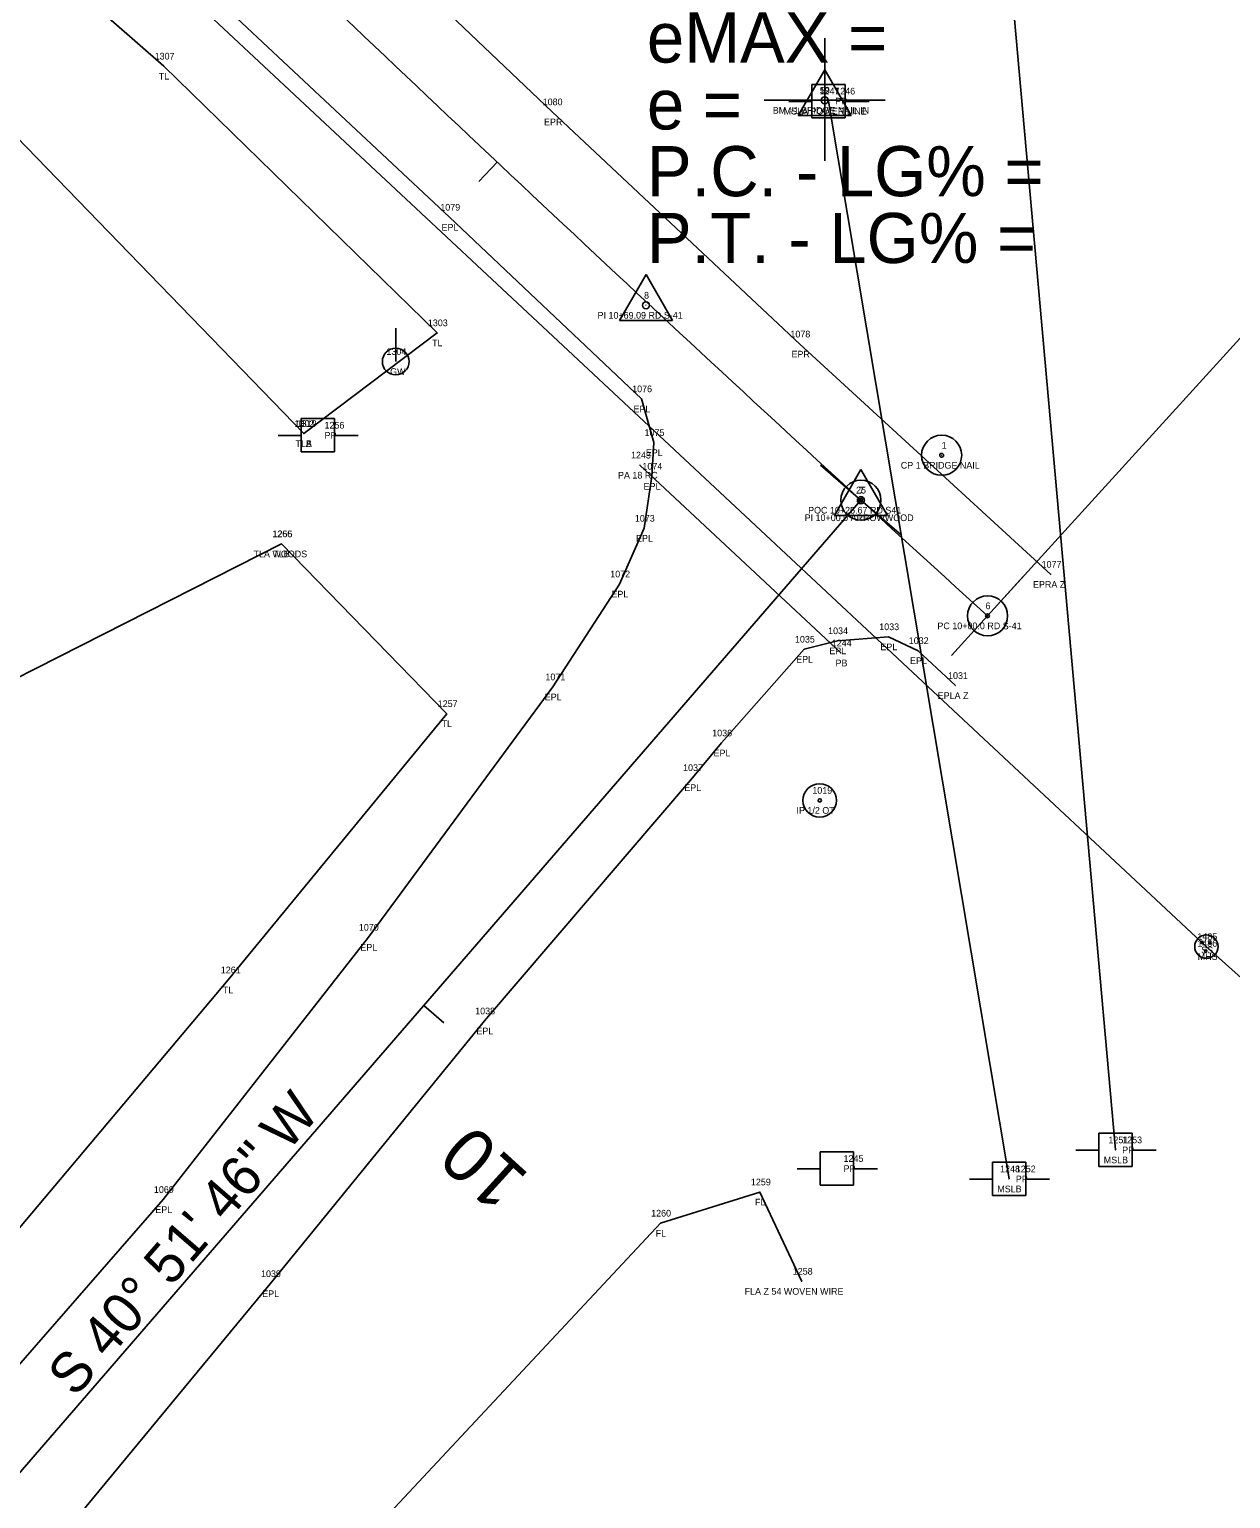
# Model space of a CAD drawing. Extents: x 1812340 to 1815011, y 1177659 to 1180159.
# Drawn here: x 1813923.6 to 1814103.3, y 1178289.1 to 1178509 of the extents above; entities that cross this region are included whole.
import ezdxf

# ---------------------------------------------------------------- set-up
doc = ezdxf.new("R2010")
doc.units = 0
for name, color, linetype in [('RD_EX_DR_Inlet', 7, 'Continuous'), ('RD_EX_DR_Pipe', 7, 'Continuous'), ('RD_EX_DR_Pipe_txCode', 7, 'Continuous'), ('RD_EX_DV_Prop_txCode', 7, 'Continuous'), ('RD_EX_DV_PropPin', 7, 'Continuous'), ('RD_EX_Fence_Other', 7, 'Continuous'), ('RD_EX_Fence_Other_txCode', 7, 'Continuous'), ('RD_EX_Misc', 7, 'Continuous'), ('RD_EX_Misc_txCode', 7, 'Continuous'), ('RD_EX_Road', 7, 'Continuous'), ('RD_EX_Road_txCode', 7, 'Continuous'), ('RD_EX_UT', 7, 'Continuous'), ('RD_EX_UT_txCode', 7, 'Continuous'), ('RD_EX_VEG', 7, 'Continuous'), ('RD_EX_VEG_txCode', 7, 'Continuous'), ('RD_HC_CL', 7, 'Continuous'), ('RD_HC_Data', 7, 'Continuous'), ('RD_HC_Data_Tic', 7, 'Continuous'), ('RD_HC_TX_Sta50', 7, 'Continuous'), ('RD_HC_txCode', 7, 'Continuous'), ('RD_SMD_Locator', 7, 'Continuous')]:
    doc.layers.add(name, color=color, linetype=linetype)

msp = doc.modelspace()

# ---------------------------------------------------------------- linework, layer by layer
at = {"layer": 'RD_EX_DR_Inlet'}
for centre, radius in [((1814099.72, 1178371.7), 1.75), ((1814099.05, 1178372.33), 0.175), ((1814100.28, 1178372.26), 0.175), ((1814099.63, 1178371.03), 0.175)]:
    msp.add_circle(centre, radius, dxfattribs=at)
at = {"layer": 'RD_EX_DR_Pipe'}
msp.add_line((1814014.96, 1178443.75), (1814045.01, 1178415.64), dxfattribs=at)
at = {"layer": 'RD_EX_DV_PropPin'}
for radius in [2.5, 0.25]:
    msp.add_circle((1814041.85, 1178393.58), radius, dxfattribs=at)
at = {"layer": 'RD_EX_Fence_Other'}
msp.add_lwpolyline([(1814039.17, 1178321.6), (1814032.91, 1178334.96), (1814018.04, 1178330.3), (1813949.86, 1178257.34), (1813966.14, 1178241)], dxfattribs=at)
at = {"layer": 'RD_EX_Misc'}
for p, q in [((1814068.17, 1178541.96), (1814086.12, 1178341.27)), ((1814043.18, 1178498.23), (1814070.2, 1178336.93))]:
    msp.add_line(p, q, dxfattribs=at)
at = {"layer": 'RD_EX_Road'}
for points in [[(1814076.45, 1178427.4), (1814038.86, 1178461.87), (1814001.83, 1178496.62), (1813965.15, 1178531.54), (1813928.08, 1178567.1), (1813892.01, 1178601.23), (1813854.54, 1178636.51), (1813817.44, 1178670.03), (1813779.87, 1178701.64)], [(1813829.87, 1178208.6), (1813830.81, 1178209.56), (1813845.51, 1178227.94), (1813874.69, 1178258.74), (1813910.02, 1178295.38), (1813943.63, 1178333.84), (1813974.31, 1178373.09), (1814001.91, 1178410.56), (1814011.9, 1178425.95), (1814015.58, 1178434.3), (1814016.71, 1178442.08), (1814017.03, 1178447.13), (1814015.19, 1178453.67), (1813986.47, 1178480.85), (1813949.15, 1178515.86)], [(1814062.16, 1178410.76), (1814056.57, 1178415.98), (1814052.15, 1178418.06), (1814044.5, 1178417.46), (1814039.53, 1178416.2), (1814027.18, 1178402.17), (1814022.8, 1178396.98), (1813991.69, 1178360.57), (1813959.64, 1178321.24), (1813927.09, 1178281.88), (1813899.48, 1178251.69), (1813888.9, 1178240.78), (1813846.63, 1178195.79)]]:
    msp.add_lwpolyline(points, dxfattribs=at)
at = {"layer": 'RD_EX_UT'}
for p, q in [((1814045.67, 1178500.74), (1814040.67, 1178500.74)), ((1814040.67, 1178500.74), (1814040.67, 1178495.74)), ((1814045.67, 1178495.74), (1814045.67, 1178500.74)), ((1814037.24, 1178498.17), (1814040.71, 1178498.17)), ((1814045.6, 1178498.17), (1814049.24, 1178498.17)), ((1814040.67, 1178495.74), (1814045.67, 1178495.74)), ((1813978.41, 1178459.26), (1813978.41, 1178464.26)), ((1813969.24, 1178450.74), (1813964.24, 1178450.74)), ((1813964.24, 1178450.74), (1813964.24, 1178445.74)), ((1813969.24, 1178445.74), (1813969.24, 1178450.74)), ((1813960.81, 1178448.18), (1813964.28, 1178448.18)), ((1813969.17, 1178448.18), (1813972.81, 1178448.18)), ((1813964.24, 1178445.74), (1813969.24, 1178445.74)), ((1814088.61, 1178343.78), (1814083.61, 1178343.78)), ((1814083.61, 1178343.78), (1814083.61, 1178338.78)), ((1814088.61, 1178338.78), (1814088.61, 1178343.78)), ((1814046.91, 1178340.99), (1814041.91, 1178340.99)), ((1814041.91, 1178340.99), (1814041.91, 1178335.99)), ((1814046.91, 1178335.99), (1814046.91, 1178340.99)), ((1814080.18, 1178341.22), (1814083.65, 1178341.22)), ((1814088.54, 1178341.22), (1814092.18, 1178341.22)), ((1814038.48, 1178338.43), (1814041.95, 1178338.43)), ((1814046.84, 1178338.43), (1814050.48, 1178338.43)), ((1814072.69, 1178339.44), (1814067.69, 1178339.44)), ((1814067.69, 1178339.44), (1814067.69, 1178334.44)), ((1814072.69, 1178334.44), (1814072.69, 1178339.44)), ((1814083.61, 1178338.78), (1814088.61, 1178338.78)), ((1814064.26, 1178336.88), (1814067.73, 1178336.88)), ((1814072.62, 1178336.88), (1814076.26, 1178336.88)), ((1814041.91, 1178335.99), (1814046.91, 1178335.99)), ((1814067.69, 1178334.44), (1814072.69, 1178334.44))]:
    msp.add_line(p, q, dxfattribs=at)
msp.add_lwpolyline([(1814122.48, 1178351.31), (1814099.73, 1178371.68), (1813807.05, 1178645.14), (1813817.45, 1178777.9), (1813883.81, 1178790.87)], dxfattribs=at)
msp.add_circle((1813978.41, 1178459.26), 2, dxfattribs=at)
at = {"layer": 'RD_EX_VEG'}
for points in [[(1813964.65, 1178448.48), (1813984.61, 1178463.55), (1813943.71, 1178503.46), (1813904.65, 1178537.57), (1813863.79, 1178578.71), (1813833.99, 1178603.93), (1813823.24, 1178594.53), (1813964.65, 1178448.48)], [(1813961.33, 1178431.97), (1813986.04, 1178406.55), (1813953.31, 1178366.71), (1813903.24, 1178307.28), (1813881.24, 1178391.37), (1813961.33, 1178431.97)]]:
    msp.add_lwpolyline(points, dxfattribs=at)
at = {"layer": 'RD_HC_CL'}
msp.add_line((1814048.02, 1178438.51), (1813851.74, 1178211.63), dxfattribs=at)
msp.add_arc((1817921.84, 1182660.75), 5730.08, 226.33932, 227.720866, dxfattribs=at)
at = {"layer": 'RD_HC_Data'}
for p, q in [((1814042.6, 1178489.32), (1814042.6, 1178507.65)), ((1814066.97, 1178421.2), (1814145.47, 1178507.54)), ((1814038.63, 1178496.06), (1814042.6, 1178502.94)), ((1814042.6, 1178502.94), (1814046.57, 1178496.06)), ((1814033.56, 1178498.36), (1814051.64, 1178498.36)), ((1814038.63, 1178496.06), (1814046.57, 1178496.06)), ((1814011.88, 1178465.39), (1814015.86, 1178472.27)), ((1814015.86, 1178472.27), (1814019.83, 1178465.39)), ((1814011.88, 1178465.39), (1814019.83, 1178465.39)), ((1814044.05, 1178436.22), (1814048.02, 1178443.1)), ((1814048.02, 1178443.1), (1814051.99, 1178436.22)), ((1814044.05, 1178436.22), (1814051.99, 1178436.22))]:
    msp.add_line(p, q, dxfattribs=at)
for centre, radius in [((1814042.6, 1178498.36), 0.529), ((1814015.86, 1178467.68), 0.529), ((1814060.1, 1178445.23), 3), ((1814060.1, 1178445.23), 0.282), ((1814048.02, 1178438.51), 3), ((1814048.02, 1178438.51), 0.529), ((1814048.02, 1178438.51), 0.282), ((1814066.97, 1178421.2), 3), ((1814066.97, 1178421.2), 0.282)]:
    msp.add_circle(centre, radius, dxfattribs=at)
at = {"layer": 'RD_HC_Data_Tic'}
for p, q in [((1813993.57, 1178489.12), (1813990.83, 1178486.21)), ((1814048.02, 1178438.51), (1814041.97, 1178443.74)), ((1814048.02, 1178438.51), (1814054.07, 1178433.28)), ((1814066.97, 1178421.2), (1814072.35, 1178427.12)), ((1814066.97, 1178421.2), (1814061.59, 1178415.28)), ((1813982.59, 1178362.88), (1813985.62, 1178360.27))]:
    msp.add_line(p, q, dxfattribs=at)
at = {"layer": 'RD_SMD_Locator'}
for centre in [(1813943.71, 1178503.46), (1814042.6, 1178498.36), (1814043.18, 1178498.23), (1814001.83, 1178496.62), (1813986.47, 1178480.85), (1814015.86, 1178467.68), (1813984.61, 1178463.55), (1814038.86, 1178461.87), (1814015.19, 1178453.67), (1813964.65, 1178448.48), (1813964.65, 1178448.48), (1814017.03, 1178447.13), (1814060.1, 1178445.23), (1814014.96, 1178443.75), (1814016.71, 1178442.08), (1814048.02, 1178438.51), (1814048.02, 1178438.51), (1814015.58, 1178434.3), (1813961.33, 1178431.97), (1813961.33, 1178431.97), (1814076.45, 1178427.4), (1814011.9, 1178425.95), (1814066.97, 1178421.2), (1814052.15, 1178418.06), (1814039.53, 1178416.2), (1814044.5, 1178417.46), (1814045.01, 1178415.64), (1814056.57, 1178415.98), (1814001.91, 1178410.56), (1814062.16, 1178410.76), (1813986.04, 1178406.55), (1814027.18, 1178402.17), (1814022.8, 1178396.98), (1813974.31, 1178373.09), (1814099.73, 1178371.68), (1813953.31, 1178366.71), (1813991.69, 1178360.57), (1814086.12, 1178341.27), (1814070.2, 1178336.93), (1814032.91, 1178334.96), (1813943.63, 1178333.84), (1814018.04, 1178330.3), (1813959.64, 1178321.24), (1814039.17, 1178321.6)]:
    msp.add_circle(centre, 0.001, dxfattribs=at)

# ---------------------------------------------------------------- texts
at = {"layer": 'RD_EX_DR_Pipe_txCode'}
for s, p in [('1243', (1814013.62, 1178444.75)), ('PA 18 RC', (1814011.67, 1178441.75)), ('1244', (1814043.66, 1178416.64)), ('PB', (1814044.23, 1178413.64))]:
    msp.add_text(s, height=1, dxfattribs=at).set_placement(p)
at = {"layer": 'RD_EX_DV_Prop_txCode'}
for s, p in [('1019', (1814040.75, 1178394.58)), ('IP 1/2 OT', (1814038.38, 1178391.58))]:
    msp.add_text(s, height=1, dxfattribs=at).set_placement(p)
at = {"layer": 'RD_EX_Fence_Other_txCode'}
for s, p in [('1259', (1814031.56, 1178335.96)), ('1260', (1814016.63, 1178331.3)), ('FL', (1814032.18, 1178332.96)), ('FL', (1814017.31, 1178328.3)), ('1258', (1814037.82, 1178322.6)), ('FLA Z 54 WOVEN WIRE', (1814030.62, 1178319.6))]:
    msp.add_text(s, height=1, dxfattribs=at).set_placement(p)
at = {"layer": 'RD_EX_Misc_txCode'}
for s, p in [('1247', (1814041.83, 1178499.23)), ('MSLA POWER LINE', (1814036.47, 1178496.23)), ('1251', (1814085.06, 1178342.27)), ('1248', (1814068.85, 1178337.93)), ('MSLB', (1814084.36, 1178339.27)), ('MSLB', (1814068.43, 1178334.93))]:
    msp.add_text(s, height=1, dxfattribs=at).set_placement(p)
at = {"layer": 'RD_EX_Road_txCode'}
for s, p in [('1080', (1814000.4, 1178497.62)), ('EPR', (1814000.6, 1178494.62)), ('1079', (1813985.08, 1178481.85)), ('EPL', (1813985.26, 1178478.85)), ('1078', (1814037.47, 1178462.87)), ('EPR', (1814037.63, 1178459.87)), ('1076', (1814013.79, 1178454.67)), ('EPL', (1814013.99, 1178451.67)), ('1075', (1814015.64, 1178448.13)), ('1074', (1814015.32, 1178443.08)), ('EPL', (1814015.83, 1178445.13)), ('EPL', (1814015.5, 1178440.08)), ('1073', (1814014.19, 1178435.3)), ('EPL', (1814014.37, 1178432.3)), ('1077', (1814075.06, 1178428.4)), ('1072', (1814010.51, 1178426.95)), ('EPRA Z', (1814073.77, 1178425.4)), ('EPL', (1814010.69, 1178423.95)), ('1033', (1814050.76, 1178419.06)), ('1035', (1814038.15, 1178417.2)), ('1034', (1814043.11, 1178418.46)), ('1032', (1814055.18, 1178416.98)), ('EPL', (1814043.29, 1178415.46)), ('EPL', (1814050.94, 1178416.06)), ('EPL', (1814038.33, 1178414.2)), ('EPL', (1814055.37, 1178413.98)), ('1071', (1814000.81, 1178411.56)), ('1031', (1814061.06, 1178411.76)), ('EPL', (1814000.71, 1178408.56)), ('EPLA Z', (1814059.51, 1178408.76)), ('1036', (1814025.77, 1178403.17)), ('EPL', (1814025.97, 1178400.17)), ('1037', (1814021.41, 1178397.98)), ('EPL', (1814021.59, 1178394.98)), ('1070', (1813972.89, 1178374.09)), ('EPL', (1813973.11, 1178371.09)), ('1038', (1813990.3, 1178361.57)), ('EPL', (1813990.48, 1178358.57)), ('1069', (1813942.22, 1178334.84)), ('EPL', (1813942.43, 1178331.84)), ('1039', (1813958.25, 1178322.24)), ('EPL', (1813958.43, 1178319.24))]:
    msp.add_text(s, height=1, dxfattribs=at).set_placement(p)
at = {"layer": 'RD_EX_UT_txCode'}
for s, p in [('1246', (1814044.18, 1178499.23)), ('PP', (1814044.18, 1178497.73)), ('1304', (1813977.02, 1178460.26)), ('GW', (1813977.57, 1178457.26)), ('1256', (1813967.75, 1178449.23)), ('PP', (1813967.75, 1178447.73)), ('1485', (1814098.37, 1178372.7)), ('1486', (1814098.36, 1178371.68)), ('SS', (1814098.95, 1178370.68)), ('MHS', (1814098.42, 1178369.7)), ('1253', (1814087.12, 1178342.27)), ('PP', (1814087.12, 1178340.77)), ('1245', (1814045.42, 1178339.48)), ('PP', (1814045.42, 1178337.98)), ('1252', (1814071.2, 1178337.93)), ('PP', (1814071.2, 1178336.43))]:
    msp.add_text(s, height=1, dxfattribs=at).set_placement(p)
at = {"layer": 'RD_EX_VEG_txCode'}
for s, p in [('1307', (1813942.33, 1178504.46)), ('TL', (1813942.94, 1178501.46)), ('1303', (1813983.22, 1178464.55)), ('TL', (1813983.84, 1178461.55)), ('1302', (1813963.27, 1178449.48)), ('1319', (1813963.59, 1178449.48)), ('TLA', (1813963.39, 1178446.48)), ('TLB', (1813963.41, 1178446.48)), ('1266', (1813959.94, 1178432.97)), ('1255', (1813959.99, 1178432.97)), ('TLA WOODS', (1813957.13, 1178429.97)), ('TLB', (1813960.09, 1178429.97)), ('1257', (1813984.69, 1178407.55)), ('TL', (1813985.27, 1178404.55)), ('1261', (1813952.23, 1178367.71)), ('TL', (1813952.54, 1178364.71))]:
    msp.add_text(s, height=1, dxfattribs=at).set_placement(p)
at = {"layer": 'RD_HC_Data'}
for s, p in [('eMAX = ', (1814016, 1178504)), ('e = ', (1814016, 1178494)), ('P.C. - LG% = ', (1814016, 1178484)), ('P.T. - LG% = ', (1814016, 1178474))]:
    msp.add_text(s, height=7.5, dxfattribs=at).set_placement(p)
msp.add_text('S 40%%d 51\' 46" W', height=6, rotation=49.1372, dxfattribs=at).set_placement((1813930.42, 1178304.1))
at = {"layer": 'RD_HC_TX_Sta50'}
msp.add_text('10', height=8, rotation=137.7209, dxfattribs=at).set_placement((1813998.6, 1178337.4))
at = {"layer": 'RD_HC_txCode'}
for s, p in [('59', (1814041.87, 1178499.36)), ('BM #1 BRIDGE NAIL IN', (1814034.83, 1178496.36)), ('8', (1814015.57, 1178468.68)), ('PI 10+69.09 RD S-41', (1814008.61, 1178465.68)), ('1', (1814060.1, 1178446.23)), ('CP 1 BRIDGE NAIL', (1814053.99, 1178443.23)), ('25', (1814047.29, 1178439.51)), ('7', (1814047.74, 1178439.51)), ('POC 10+25.67 RD S41', (1814040.12, 1178436.51)), ('PI 10+00.0 ARROWWOOD', (1814039.6, 1178435.38)), ('6', (1814066.66, 1178422.2)), ('PC 10+00.0 RD S-41', (1814059.47, 1178419.2))]:
    msp.add_text(s, height=1, dxfattribs=at).set_placement(p)

doc.saveas('drawing.dxf')
